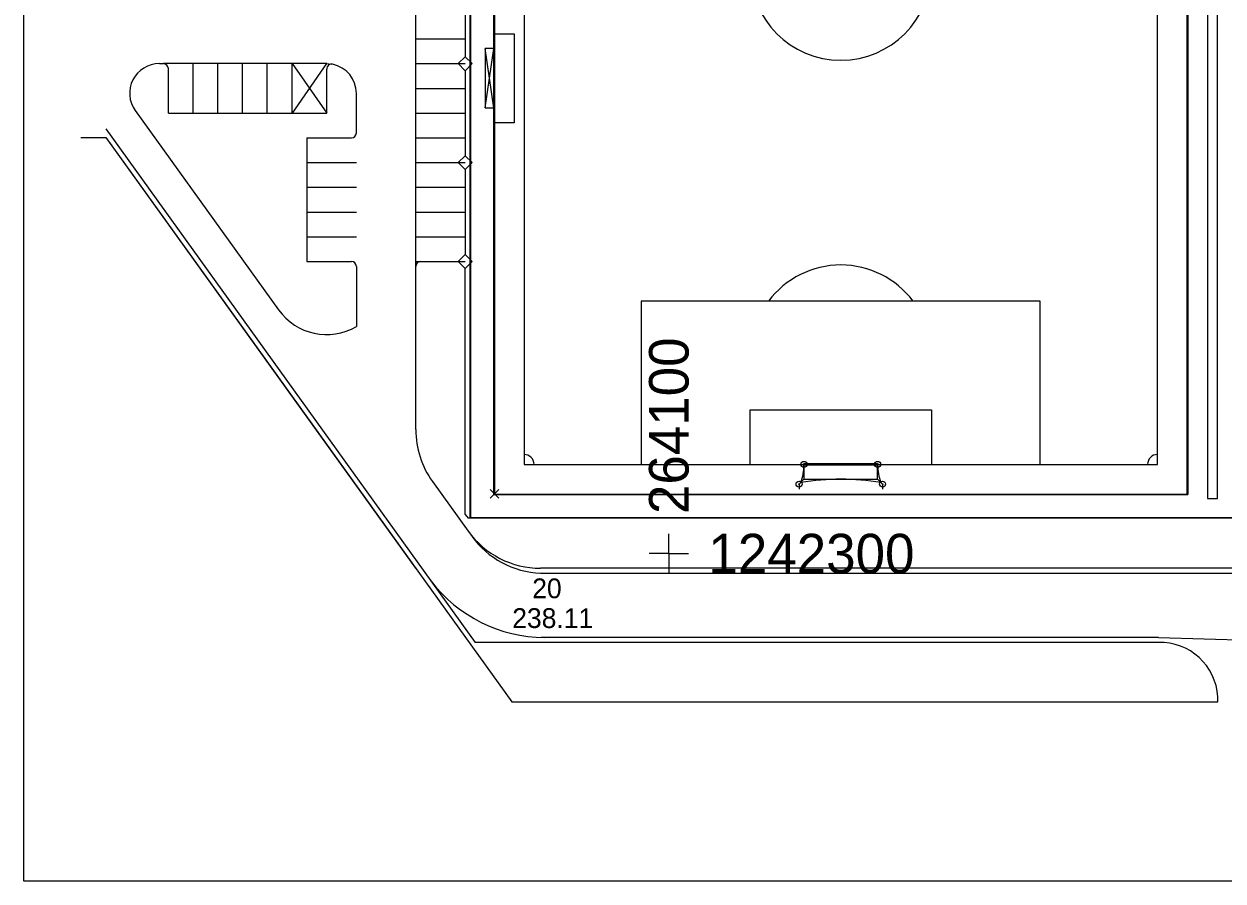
# Model space of a CAD drawing. Extents: x -264165 to -263575, y -1242333 to -1242036.
# Drawn here: x -264165.2 to -264044, y -1242333.1 to -1242246.5 of the extents above; entities that cross this region are included whole.
import ezdxf

# ---------------------------------------------------------------- set-up
doc = ezdxf.new("R2010")
doc.units = 0
for name, color, linetype in [('KFA_BODY_VYTYCOVAK', 7, 'Continuous'), ('KFA_HEKT_SIET_1-1000', 7, 'Continuous'), ('KFA_SITUACIA_DRS_VYTYCOVAK_SEDA', 7, 'Continuous'), ('RAM_NA_TLAC', 7, 'Continuous')]:
    doc.layers.add(name, color=color, linetype=linetype)

msp = doc.modelspace()

# ---------------------------------------------------------------- linework, layer by layer
at = {"layer": 'KFA_BODY_VYTYCOVAK'}
for p, q in [((-264118.05, -1242294.41), (-264117.17, -1242293.53)), ((-264117.17, -1242294.41), (-264118.05, -1242293.53))]:
    msp.add_line(p, q, dxfattribs=at)
at = {"layer": 'KFA_HEKT_SIET_1-1000'}
for q in [(-264100, -1242298), (-264102, -1242300), (-264098, -1242300), (-264100, -1242302)]:
    msp.add_line((-264100, -1242300), q, dxfattribs=at)
at = {"layer": 'KFA_SITUACIA_DRS_VYTYCOVAK_SEDA'}
for p, q in [((-264120.07, -1242296.43), (-264120.07, -1242185.98)), ((-264120.02, -1242296.38), (-264120.02, -1242186.03)), ((-264117.67, -1242187.93), (-264117.67, -1242291.74)), ((-264117.67, -1242294.03), (-264117.67, -1242187.93)), ((-264117.62, -1242187.98), (-264117.62, -1242291.72)), ((-264047.62, -1242293.98), (-264047.62, -1242187.98)), ((-264047.57, -1242294.03), (-264047.57, -1242187.93)), ((-264047.57, -1242187.93), (-264047.57, -1242294.03)), ((-264045.57, -1242187.53), (-264045.57, -1242294.43)), ((-264044.57, -1242294.43), (-264044.57, -1242187.53)), ((-264125.57, -1242270.98), (-264125.57, -1242191.48)), ((-264114.62, -1242190.98), (-264114.62, -1242290.98)), ((-264050.62, -1242290.98), (-264050.62, -1242190.98)), ((-264120.57, -1242241.19), (-264120.57, -1242249.77)), ((-264125.57, -1242247.98), (-264120.57, -1242247.98)), ((-264117.62, -1242247.46), (-264115.62, -1242247.46)), ((-264115.62, -1242247.46), (-264115.62, -1242256.46)), ((-264121.27, -1242250.48), (-264120.57, -1242249.78)), ((-264120.57, -1242249.78), (-264119.86, -1242250.48)), ((-264118.57, -1242254.96), (-264117.67, -1242248.96)), ((-264117.67, -1242254.96), (-264118.57, -1242248.96)), ((-264118.57, -1242248.96), (-264118.57, -1242254.96)), ((-264117.67, -1242248.96), (-264118.57, -1242248.96)), ((-264117.67, -1242254.96), (-264117.67, -1242248.96)), ((-264151.48, -1242250.48), (-264151.07, -1242250.48)), ((-264150.57, -1242250.48), (-264151.07, -1242250.48)), ((-264134.57, -1242250.48), (-264150.57, -1242250.48)), ((-264150.57, -1242255.48), (-264150.57, -1242250.98)), ((-264148.07, -1242255.48), (-264148.07, -1242250.48)), ((-264145.57, -1242255.48), (-264145.57, -1242250.48)), ((-264143.07, -1242255.48), (-264143.07, -1242250.48)), ((-264140.57, -1242255.48), (-264140.57, -1242250.48)), ((-264138.07, -1242255.48), (-264138.07, -1242250.48)), ((-264134.58, -1242250.48), (-264138.07, -1242255.48)), ((-264138.07, -1242250.48), (-264134.57, -1242255.48)), ((-264134.58, -1242250.48), (-264134.07, -1242250.53)), ((-264125.57, -1242250.48), (-264120.57, -1242250.48)), ((-264120.57, -1242251.19), (-264121.27, -1242250.48)), ((-264119.86, -1242250.48), (-264120.57, -1242251.19)), ((-264134.57, -1242255.48), (-264134.57, -1242251.03)), ((-264120.57, -1242251.19), (-264120.57, -1242259.78)), ((-264125.57, -1242252.98), (-264120.57, -1242252.98)), ((-264131.57, -1242257.48), (-264131.57, -1242253.48)), ((-264153.92, -1242255.23), (-264139.44, -1242275.36)), ((-264150.57, -1242255.48), (-264134.57, -1242255.48)), ((-264125.57, -1242255.48), (-264120.57, -1242255.48)), ((-264118.57, -1242254.96), (-264117.67, -1242254.96)), ((-264115.62, -1242256.46), (-264117.62, -1242256.46)), ((-264159.4, -1242257.95), (-264156.9, -1242257.95)), ((-264156.9, -1242257.08), (-264119.57, -1242308.98)), ((-264156.9, -1242257.94), (-264115.87, -1242314.98)), ((-264156.9, -1242257.94), (-264137.78, -1242284.52)), ((-264136.57, -1242257.98), (-264136.57, -1242270.48)), ((-264136.57, -1242257.98), (-264132.07, -1242257.98)), ((-264125.57, -1242257.98), (-264120.57, -1242257.98)), ((-264136.57, -1242260.48), (-264131.57, -1242260.48)), ((-264125.57, -1242260.48), (-264120.57, -1242260.48)), ((-264121.27, -1242260.48), (-264120.57, -1242259.78)), ((-264120.57, -1242261.19), (-264121.27, -1242260.48)), ((-264120.57, -1242259.78), (-264119.86, -1242260.48)), ((-264119.86, -1242260.48), (-264120.57, -1242261.19)), ((-264120.57, -1242261.19), (-264120.57, -1242269.77)), ((-264136.57, -1242262.98), (-264131.57, -1242262.98)), ((-264125.57, -1242262.98), (-264120.57, -1242262.98)), ((-264136.57, -1242265.48), (-264131.57, -1242265.48)), ((-264125.57, -1242265.48), (-264120.57, -1242265.48)), ((-264136.57, -1242267.98), (-264131.57, -1242267.98)), ((-264125.57, -1242267.98), (-264120.57, -1242267.98)), ((-264121.27, -1242270.48), (-264120.57, -1242269.78)), ((-264120.57, -1242269.78), (-264119.86, -1242270.48)), ((-264136.57, -1242270.48), (-264132.07, -1242270.48)), ((-264131.57, -1242270.98), (-264131.57, -1242277.06)), ((-264125.57, -1242270.48), (-264120.57, -1242270.48)), ((-264125.57, -1242287.47), (-264125.57, -1242270.98)), ((-264125.07, -1242270.48), (-264121.27, -1242270.48)), ((-264120.57, -1242271.19), (-264121.27, -1242270.48)), ((-264119.86, -1242270.48), (-264120.57, -1242271.19)), ((-264120.57, -1242296.04), (-264120.57, -1242271.19)), ((-264062.46, -1242274.48), (-264102.78, -1242274.48)), ((-264102.78, -1242274.48), (-264102.78, -1242290.98)), ((-264062.46, -1242290.98), (-264062.46, -1242274.48)), ((-264137.78, -1242284.52), (-264125.58, -1242301.48)), ((-264091.78, -1242290.98), (-264091.78, -1242285.48)), ((-264091.78, -1242285.48), (-264073.46, -1242285.48)), ((-264073.46, -1242285.48), (-264073.46, -1242290.98)), ((-264114.62, -1242290.98), (-264050.62, -1242290.98)), ((-264102.78, -1242290.98), (-264091.78, -1242290.98)), ((-264078.9, -1242290.92), (-264086.34, -1242290.92)), ((-264086.34, -1242290.98), (-264086.34, -1242292.48)), ((-264078.9, -1242292.48), (-264078.9, -1242290.98)), ((-264073.46, -1242290.98), (-264062.46, -1242290.98)), ((-264117.67, -1242291.74), (-264117.67, -1242294.03)), ((-264117.62, -1242291.72), (-264117.62, -1242293.98)), ((-264086.34, -1242291.04), (-264078.9, -1242291.04)), ((-264078.9, -1242291.04), (-264086.34, -1242291.04)), ((-264123.87, -1242292.72), (-264120.27, -1242297.74)), ((-264086.34, -1242292.48), (-264086.84, -1242292.98)), ((-264086.84, -1242292.98), (-264086.84, -1242293.5)), ((-264086.34, -1242292.48), (-264078.9, -1242292.48)), ((-264078.9, -1242292.48), (-264078.4, -1242292.98)), ((-264078.4, -1242292.98), (-264078.4, -1242293.5)), ((-264117.67, -1242294.03), (-264047.57, -1242294.03)), ((-264047.57, -1242294.03), (-264117.67, -1242294.03)), ((-264117.62, -1242293.98), (-264047.62, -1242293.98)), ((-264045.57, -1242294.43), (-264044.57, -1242294.43)), ((-264120.57, -1242296.04), (-264120.28, -1242296.43)), ((-264120.02, -1242296.43), (-264120.28, -1242296.43)), ((-263970.07, -1242296.43), (-264120.07, -1242296.43)), ((-263970.12, -1242296.38), (-264120.02, -1242296.38)), ((-263965.14, -1242296.43), (-264120.02, -1242296.43)), ((-263971.07, -1242301.48), (-264112.96, -1242301.48)), ((-264112.96, -1242301.98), (-263971.81, -1242301.98)), ((-264050.53, -1242308.98), (-264119.57, -1242308.98)), ((-264050.53, -1242308.48), (-264112.91, -1242308.48)), ((-264050.53, -1242308.48), (-264032.14, -1242309.01)), ((-264115.89, -1242314.98), (-264044.53, -1242314.98)), ((-264044.53, -1242314.98), (-264044.53, -1242314.48))]:
    msp.add_line(p, q, dxfattribs=at)
for centre, radius in [((-264086.34, -1242290.98), 0.3), ((-264086.34, -1242290.98), 0.06), ((-264086.34, -1242290.98), 0.055), ((-264078.9, -1242290.98), 0.3), ((-264078.9, -1242290.98), 0.06), ((-264078.9, -1242290.98), 0.055), ((-264086.84, -1242292.98), 0.3), ((-264086.84, -1242292.98), 0.03), ((-264086.84, -1242292.98), 0.0275), ((-264078.4, -1242292.98), 0.3), ((-264078.4, -1242292.98), 0.03), ((-264078.4, -1242292.98), 0.0275)]:
    msp.add_circle(centre, radius, dxfattribs=at)
for centre, radius, start, end in [((-264082.62, -1242240.98), 9.15, 180, 360), ((-264151.48, -1242253.48), 3, 90, 215.724), ((-264151.07, -1242250.98), 0.5, 0, 90), ((-264134.07, -1242251.03), 0.5, 78.463, 180), ((-264134.57, -1242253.48), 3, 0, 78.463), ((-264132.07, -1242257.48), 0.5, 270, 0), ((-264132.07, -1242270.98), 0.5, 0, 90), ((-264125.07, -1242270.98), 0.5, 90, 180), ((-264082.62, -1242279.98), 9.15, 36.9482, 143.0518), ((-264134.57, -1242271.86), 6, 215.724, 300), ((-264116.57, -1242287.47), 9, 180, 215.724), ((-264114.62, -1242290.98), 1, 0, 90), ((-264050.62, -1242290.98), 1, 90, 180), ((-264091.31, -1242291.02), 4.97, 338.8391, 359.7852), ((-264073.93, -1242291.02), 4.97, 180.2148, 201.1609), ((-264082.62, -1242317.19), 24.71, 80.5546, 99.4453), ((-264112.96, -1242292.48), 9, 215.724, 270), ((-264112.56, -1242292.92), 9.07, 215.874, 267.4682), ((-264112.43, -1242293.84), 14.64, 217.6201, 269.4957), ((-264050.35, -1242314.8), 5.83, 3.1701, 91.809)]:
    msp.add_arc(centre, radius, start, end, dxfattribs=at)
at = {"layer": 'RAM_NA_TLAC'}
msp.add_lwpolyline([(-264165.16, -1242333.09), (-264165.16, -1242036.09), (-263955.16, -1242036.09), (-263575.16, -1242036.09), (-263575.16, -1242333.09), (-263955.16, -1242333.09)], close=True, dxfattribs=at)

# ---------------------------------------------------------------- texts
at = {"layer": 'KFA_BODY_VYTYCOVAK'}
for s, p in [('20', (-264113.8, -1242304.51)), ('238.11', (-264115.82, -1242307.52))]:
    msp.add_text(s, height=2, dxfattribs=at).set_placement(p)
at = {"layer": 'KFA_HEKT_SIET_1-1000'}
msp.add_text('264100', height=4, rotation=90, dxfattribs=at).set_placement((-264098, -1242296))
msp.add_text('1242300', height=4, dxfattribs=at).set_placement((-264096, -1242302))

doc.saveas('drawing.dxf')
